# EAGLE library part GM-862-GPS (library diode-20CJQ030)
TELIT GM-862-GPS quad band GSM module with GPS Description:
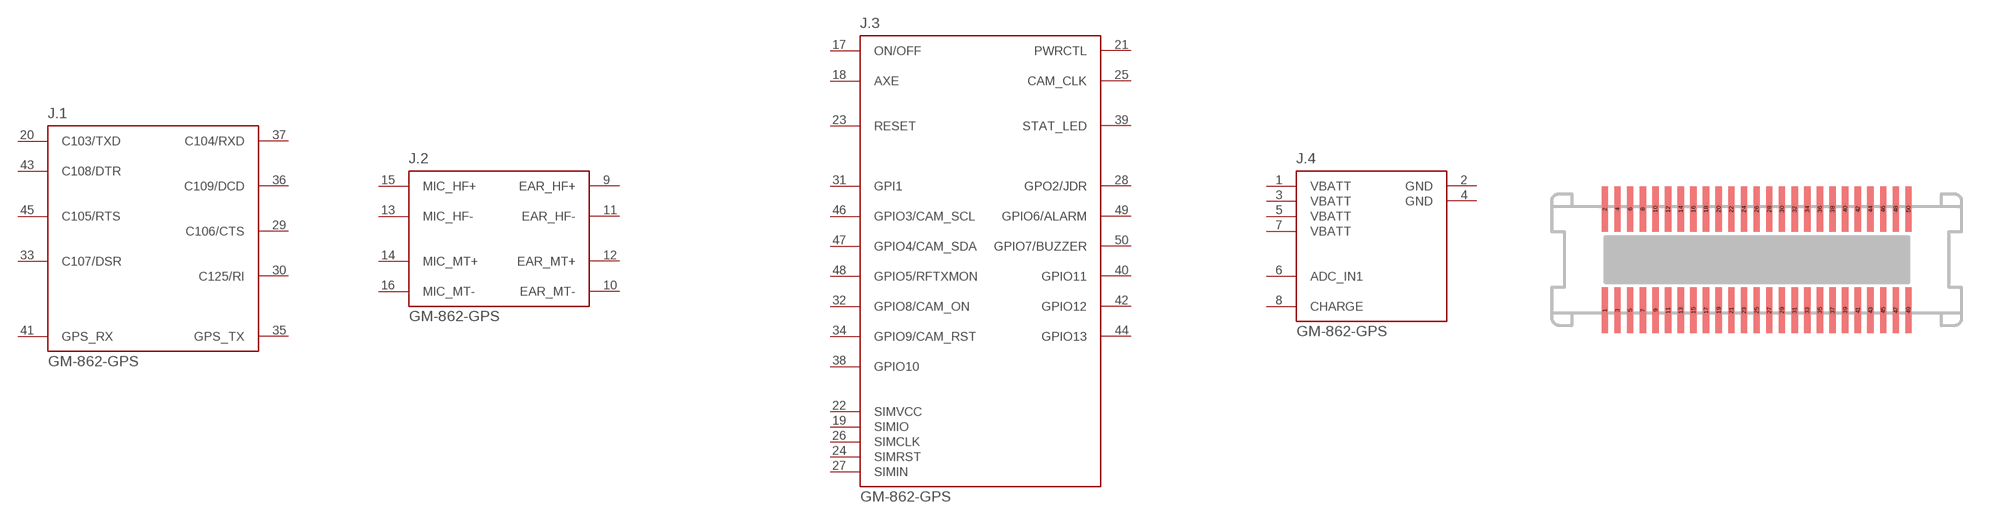
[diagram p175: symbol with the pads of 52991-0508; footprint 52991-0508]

Designator prefix J; gates .1=GM862-GPS-COM .2=GM862-GPS-ANALOG .3=GM862-GPS-CTRL .4=GM862-GPS-PWR

## GM-862-GPS  [52991-0508]
1  .4:VBATT  pwr
2  .4:GND  pwr
3  .4:VBATT  pwr
4  .4:GND  pwr
5  .4:VBATT  pwr
6  .4:ADC_IN1  in
7  .4:VBATT  pwr
8  .4:CHARGE  in
9  .2:EAR_HF+  out
10  .2:EAR_MT-  out
11  .2:EAR_HF-  out
12  .2:EAR_MT+  out
13  .2:MIC_HF-  out
14  .2:MIC_MT+  out
15  .2:MIC_HF+  out
16  .2:MIC_MT-  out
17  .3:ON/OFF  in
18  .3:AXE  in
19  .3:SIMIO
20  .1:C103/TXD  pas
21  .3:PWRCTL  out
22  .3:SIMVCC
23  .3:RESET  in
24  .3:SIMRST
25  .3:CAM_CLK  out
26  .3:SIMCLK
27  .3:SIMIN
28  .3:GPO2/JDR  out
29  .1:C106/CTS  pas
30  .1:C125/RI  pas
31  .3:GPI1  in
32  .3:GPIO8/CAM_ON
33  .1:C107/DSR  pas
34  .3:GPIO9/CAM_RST
35  .1:GPS_TX  out
36  .1:C109/DCD  pas
37  .1:C104/RXD  pas
38  .3:GPIO10
39  .3:STAT_LED  out
40  .3:GPIO11
41  .1:GPS_RX  in
42  .3:GPIO12
43  .1:C108/DTR  pas
44  .3:GPIO13
45  .1:C105/RTS  pas
46  .3:GPIO3/CAM_SCL
47  .3:GPIO4/CAM_SDA
48  .3:GPIO5/RFTXMON
49  .3:GPIO6/ALARM
50  .3:GPIO7/BUZZER

## Footprint 52991-0508 (pad centres in mm)
Molex board to board connector
smd 0.25 x 1.8: 1 -6,-2; 2 -6,2; 3 -5.5,-2; 4 -5.5,2; 5 -5,-2; 6 -5,2; 7 -4.5,-2; 8 -4.5,2; 9 -4,-2; 10 -4,2; 11 -3.5,-2; 12 -3.5,2; 13 -3,-2; 14 -3,2; 15 -2.5,-2; 16 -2.5,2; 17 -2,-2; 18 -2,2; 19 -1.5,-2; 20 -1.5,2; 21 -1,-2; 22 -1,2; 23 -0.5,-2; 24 -0.5,2; 25 0,-2; 26 0,2; 27 0.5,-2; 28 0.5,2; 29 1,-2; 30 1,2; 31 1.5,-2; 32 1.5,2; 33 2,-2; 34 2,2; 35 2.5,-2; 36 2.5,2; 37 3,-2; 38 3,2; 39 3.5,-2; 40 3.5,2; 41 4,-2; 42 4,2; 43 4.5,-2; 44 4.5,2; 45 5,-2; 46 5,2; 47 5.5,-2; 48 5.5,2; 49 6,-2; 50 6,2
